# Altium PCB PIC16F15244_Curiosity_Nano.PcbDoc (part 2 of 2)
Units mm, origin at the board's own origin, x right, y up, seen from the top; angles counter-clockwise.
Board outline 50.8 x 20.32 mm, 4 copper layers (Top-Layer, Ground Plane, Power Plane, Bottom Layer), stack 1.59 mm thick; 59 components, 67 nets, 348 pads, 148 vias.
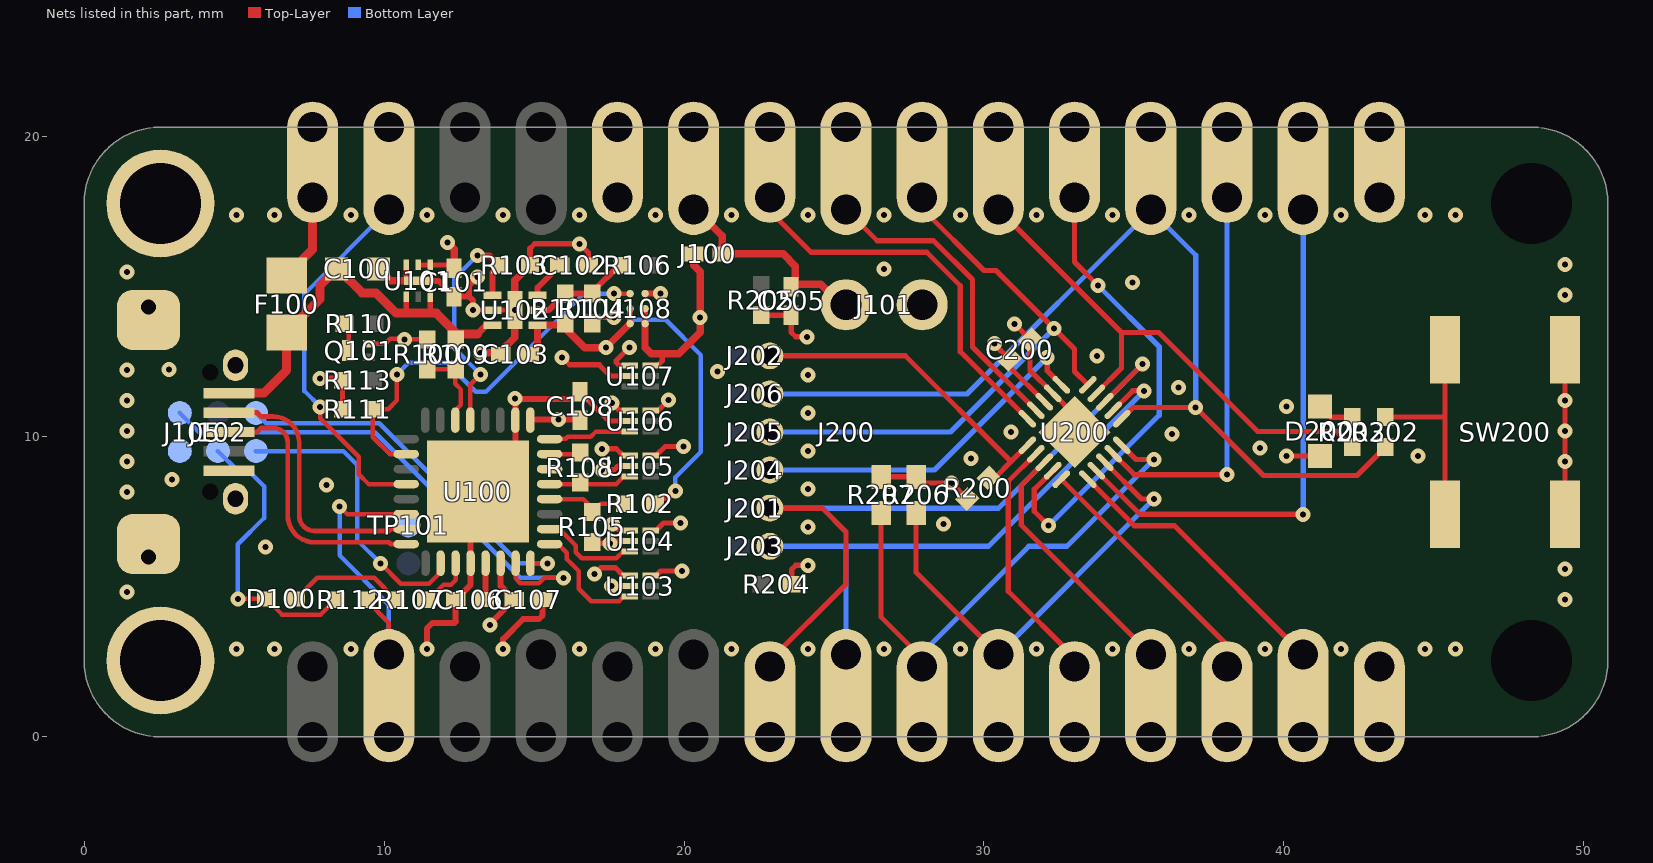
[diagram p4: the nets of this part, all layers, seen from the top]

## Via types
v1: diameter 0.5, hole 0.2, Top-Layer to Bottom Layer, 144 vias
v2: diameter 0.5, hole 0.2, Top-Layer to Bottom Layer, tented both sides, 2 vias
v3: diameter 0.5, hole 0.2, Top-Layer to Bottom Layer, tented top, 2 vias

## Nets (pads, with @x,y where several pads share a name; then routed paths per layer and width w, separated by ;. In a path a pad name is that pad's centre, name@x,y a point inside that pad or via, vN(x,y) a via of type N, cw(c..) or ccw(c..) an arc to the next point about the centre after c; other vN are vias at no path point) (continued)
GND: C100.1 C101.1 C102.2 C103.1 C106.1 C107.2 C108.2 C200.2 C205.2 J102.2 J105.5 J200.15 J200.16 J200.26 pad.666 Q101.2 R100.2 R103.2 R104.1 R105.1 R111.2 R113.2 R204.2 R205.2 SW200.1 SW200.2 TP101.1 U100.10 U100.28 U100.33 U101.3 U101.7 U102.2 U102.7 U103.2 U104.2 U105.2 U106.2 U107.2 U108.C1 U200.17 U200.21 | length 54.1
  Top-Layer w0.15: Q101.2@9.5,13.1 10.035,13.1 10.21,13.275 10.65,13.275 v1(10.675,13.25) R100.2@11.439,13.25
  Top-Layer w0.175: v1(7.87,11.95) 8.619,11.95 R111.2@8.619,10.922 ; U101.3@10.739,15.725 10.739,15.2 U101.7@11.139,15.2 ; v1(12.965,14.225) U102.2@13.615,14.225 v1(14.365,14.225) ; 14.865,16.275 15.026,16.436 15.615,16.436 v1(16.517,16.436) 16.815,16.138 C102.2@16.815,15.725 ; v1(15.94,12.65) 16.19,12.4 17.17,12.4 17.545,12.025 U107.2@18.189,12.025 ; C108.2@16.518,11.5 17.493,10.525 U106.2@18.189,10.525 ; R104.1@16.94,13.775 17.14,13.975 v1(17.659,13.975) ; R105.1@17.015,6.525 17.09,6.45 v1(17.54,6.45) 17.615,6.525 U104.2@18.189,6.525 ; v1(17.264,8.9) 17.677,8.9 17.803,9.025 U105.2@18.189,9.025 ; v1(17.59,5.025) U103.2@18.189,5.025 ; R205.2@22.581,14.054 23.571,14.054 23.571,13.487 23.724,13.335 v1(24.105,13.335) ; R204.2@23.589,5.085 23.589,5.58 23.724,5.715 v1(24.13,5.715) ; v1(31.013,13.767) C200.2@31.534,13.246 ; C200.2@31.533,13.245 31.533,12.213 U200.17@32.295,11.45 33.02,10.726 U200.21@33.02,10.16 ; SW200.2@49.371,7.41 v1(49.371,9.173) v1(49.371,10.189) v1(49.371,11.205) SW200.1@49.371,12.91
  Top-Layer w0.2: U101.7@11.139,15.2 11.814,15.2 C101.1@12.339,14.675 12.84,14.675 ; v1(11.43,2.921) 11.43,3.615 11.615,3.8 12.343,3.8 12.393,3.85 12.39,3.853 C106.1@12.39,4.575 12.884,5.069 U100.28@12.884,5.787 12.884,7.909 U100.33@13.139,8.164 ; v1(12.965,14.225) 12.965,14.55 12.84,14.675 ; v1(13.115,15.325) 12.84,15.05 12.84,14.675 ; U100.33@13.149,8.174 14.376,9.401 U100.10@14.376,10.556 14.376,11.112 14.523,11.259 16.277,11.259 C108.2@16.518,11.5 ; v1(13.97,2.921) 13.97,3.255 14.64,3.925 15.165,3.925 15.29,4.05 C107.2@15.29,4.575 ; R103.2@14.865,15.725 14.865,16.275 ; U108.C1@18.702,14.775 v1(19.215,14.775)
  Top-Layer w0.25: C100.1@9.816,15.597 10.214,15.2 U101.7@10.739,15.2 ; v1@13.165,12.8 v1(13.215,12.8) C103.1@13.895,12.8 ; C103.1@13.895,12.75 C103.1@13.895,12.8 ; R103.2@14.865,15.725 14.365,15.225 v1(14.365,14.225) 14.365,13.317 13.895,12.847 C103.1@13.895,12.8
  other v1: 5.08,2.921 6.35,2.921 8.89,2.921 16.51,2.921 19.05,2.921 21.59,2.921 24.13,2.921 26.67,2.921 29.21,2.921 31.75,2.921 34.29,2.921 36.83,2.921 39.37,2.921 41.91,2.921 44.704,2.921 45.72,2.921 49.371,4.572 1.429,4.826 49.371,5.588 24.13,6.985 28.651,7.087 1.429,8.157 24.13,8.255 2.925,8.575 1.429,9.173 29.562,9.276 44.475,9.356 24.13,9.525 39.205,9.63 36.271,10.089 30.893,10.168 1.429,10.189 24.13,10.795 40.081,11.006 1.429,11.205 14.373,11.284 36.478,11.647 24.13,12.065 21.115,12.175 1.429,12.221 2.825,12.238 33.77,12.7 49.371,14.732 34.956,15.151 1.429,15.494 26.67,15.596 49.371,15.748 5.08,17.399 6.35,17.399 8.89,17.399 11.43,17.399 13.97,17.399 16.51,17.399 19.05,17.399 21.59,17.399 24.13,17.399 26.67,17.399 29.21,17.399 31.75,17.399 34.29,17.399 36.83,17.399 39.37,17.399 41.91,17.399 44.704,17.399 45.72,17.399
  other v2: 6.05,6.325 8.088,8.4
ID_SYS: J200.2 R112.2 U100.22 | length 10.5
  Top-Layer w0.15: v1(8.515,7.675) 8.766,7.424 U100.22@10.74,7.424 ; R112.2@9.39,4.575 10.16,3.805 J200.2@10.16,2.743 J200.2@10.16,2.54
  Bottom Layer w0.15: v1(8.515,7.675) 8.515,6.05 10.16,4.405 J200.2@10.16,2.54
NetC102_1: C102.1 U102.6 | length 1.3
  Top-Layer w0.2: U102.6@15.115,14.725 15.115,14.975 C102.1@15.865,15.725
NetD100_1: D100.1 R107.1 | length 3.9
  Top-Layer w0.15: D100.1@7.071,4.6 7.768,5.297 9.669,5.297 R107.1@10.39,4.575
NetD200_1: D200.1 R203.2 | length 1.2
  Top-Layer w0.175: D200.1@41.201,11.006 41.551,10.656 R203.2@42.28,10.656
NetQ101_3: Q101.3 R110.1 | length 1
  Top-Layer w0.15: R110.1@8.674,13.7 8.815,13.559 Q101.3@8.815,12.8
NetR202_2: R202.2 SW200.3 SW200.4 | length 7.5
  Top-Layer w0.175: R202.2@43.385,10.656 45.371,10.656 ; SW200.4@45.371,7.41 45.371,10.656 ; SW200.3@45.371,12.91 45.371,10.656
RA0_ICSPDAT: J204.2 U200.16 | length 11.9
  Top-Layer w0.175: v1(32.106,12.649) 32.106,12.206 U200.16@32.578,11.733
  Bottom Layer w0.175: J204.2@22.86,8.89 28.346,8.89 v1(32.106,12.649)
RA1_ICSPCLK_ANA1: J200.22 J205.2 U200.15 | length 19.7
  Top-Layer w0.175: J200.22@27.94,17.983 27.94,17.602 29.997,15.545 30.404,15.545 v1(32.334,13.614) 33.02,12.929 33.02,12.175 U200.15@33.462,11.733
  Bottom Layer w0.175: J205.2@22.86,10.16 28.88,10.16 v1(32.334,13.614)
RA2_LED0_ANA2: J200.21 R203.1 U200.14 | length 17.5
  Top-Layer w0.175: J200.21@30.48,17.577 34.582,13.475 ; U200.14@33.745,11.45 34.582,12.288 34.582,13.475 ; R203.1@42.28,9.656 41.761,10.175 39.126,10.175 35.827,13.475 34.582,13.475
RA3_M\C\L\R\: J202.2 R200.2 U200.1 | length 11.3
  Top-Layer w0.175: J202.2@22.86,12.7 27.375,12.7 30.902,9.173 ; R200.2@30.072,8.629 30.357,8.629 30.902,9.173 ; U200.1@31.447,9.718 30.902,9.173
RA4_ANA4: J200.24 U200.20 | length 13.2
  Top-Layer w0.175: J200.24@22.86,17.983 22.86,17.526 24.232,16.154 28.092,16.154 29.21,15.037 29.21,12.839 U200.20@31.447,10.602
RA5_ANA5: J200.23 U200.19 | length 10.4
  Top-Layer w0.175: J200.23@25.4,17.577 26.441,16.535 28.321,16.535 29.616,15.24 29.616,12.998 U200.19@31.73,10.885
RB4_I2C_SDA: J200.9 R207.2 U200.10 | length 19.6
  Top-Layer w0.16: R207.2@26.568,7.468 26.568,3.988 27.94,2.616 J200.9@27.94,2.337 J200.9@27.94,0.508
  Top-Layer w0.175: U200.10@34.593,9.718 35.066,9.246 v1(35.662,9.246)
  Bottom Layer w0.175: J200.9@27.94,2.337 27.94,2.794 31.496,6.35 32.766,6.35 v1(35.662,9.246)
RB5_ANB5: J200.18 U200.9 | length 13.3
  Top-Layer w0.175: U200.9@34.31,9.435 35.008,8.738 v1(38.1,8.738)
  Bottom Layer w0.175: v1(38.1,8.738) J200.18@38.1,17.983
RB6_I2C_SCL: J200.10 R206.2 U200.8 | length 17.2
  Top-Layer w0.175: R206.2@27.737,7.468 27.737,5.486 J200.10@30.48,2.743 J200.10@30.48,0.855 ; U200.8@34.028,9.152 35.255,7.925 v1(35.662,7.925)
  Bottom Layer w0.175: J200.10@30.48,2.743 v1(35.662,7.925)
RB7_ANB7: J200.17 U200.7 | length 17.7
  Top-Layer w0.175: U200.7@33.745,8.87 35.198,7.417 v1(40.64,7.417)
  Bottom Layer w0.175: v1(40.64,7.417) J200.17@40.64,17.577
RC0_UART_TX: J200.7 J201.2 U200.13 | length 24.6
  Top-Layer w0.175: J200.7@22.86,2.337 22.86,2.54 25.4,5.08 25.4,6.831 24.611,7.62 J201.2@22.86,7.62 ; U200.13@34.028,11.168 v1(35.281,12.421)
  Bottom Layer w0.175: J201.2@22.86,7.62 30.48,7.62 v1(35.281,12.421)
RC1_UART_RX: J200.8 J203.2 U200.12 | length 19.5
  Top-Layer w0.175: U200.12@34.31,10.885 34.957,11.532 v1(35.331,11.532)
  Bottom Layer w0.175: J203.2@22.86,6.35 25.4,6.35 ; J200.8@25.4,2.743 25.4,6.35 ; v1(35.331,11.532) 30.15,6.35 25.4,6.35
RC2_SW0_ANC2: J200.19 J206.2 R202.1 U200.11 | length 32.7
  Top-Layer w0.175: U200.11@34.593,10.602 34.964,10.973 v1(37.059,10.973) 39.319,8.712 42.441,8.712 R202.1@43.385,9.656
  Bottom Layer w0.175: J206.2@22.86,11.43 29.439,11.43 35.56,17.551 37.059,16.053 v1(37.059,10.973)
RC3_ANC3: J200.20 U200.4 | length 16.4
  Top-Layer w0.175: v1(32.156,7.036) 31.674,7.518 31.674,8.248 U200.4@32.295,8.87 ; J200.20@33.02,17.983 33.02,15.824 v1(33.807,15.037)
  Bottom Layer w0.175: v1(32.156,7.036) 35.839,10.719 35.839,13.005 v1(33.807,15.037) ; J200.20@33.02,17.526 J200.20@33.02,17.983
RC4_SPI_MISO: J200.12 U200.3 | length 8.5
  Top-Layer w0.175: U200.3@32.012,9.152 31.242,8.382 31.242,7.061 J200.12@35.56,2.743
RC5_SPI_MOSI: J200.11 U200.2 | length 8.4
  Top-Layer w0.175: U200.2@31.73,9.435 30.81,8.516 30.81,4.851 33.02,2.642 J200.11@33.02,2.337
RC6_SPI_SCK: J200.13 U200.5 | length 8.5
  Top-Layer w0.175: U200.5@32.578,8.587 38.1,3.065 J200.13@38.1,2.337
RC7_SPI_SS: J200.14 U200.6 | length 9.6
  Top-Layer w0.175: U200.6@33.462,8.587 35.013,7.036 36.347,7.036 J200.14@40.64,2.743
REG_ADJUST: R101.2 R104.2 R106.1 U102.5 | length 3.4
  Top-Layer w0.2: U102.5@15.115,14.225 15.49,14.225 R101.2@16.04,14.775 16.965,14.775 16.965,14.85 R106.1@17.84,15.725
REG_ENABLE: R103.1 U100.13 U102.1 | length 8.3
  Top-Layer w0.15: U100.13@12.876,10.556 12.876,11.736 v1(13.215,12.075)
  Top-Layer w0.2: v1(13.115,16.05) 13.508,16.05 13.833,15.725 R103.1@13.865,15.725 13.615,15.475 U102.1@13.615,14.725
  Bottom Layer w0.15: v1(13.115,16.05) 12.34,15.275 12.34,12.95 v1(13.215,12.075)
RESERVED: U100.6
S0_0_RX: R108.1 U100.5 U105.3 | length 2.8
  Top-Layer w0.15: U100.5@15.52,8.424 17.74,8.424 17.991,8.675 U105.3@18.189,8.675
S0_2_TX: R108.2 U100.7 | length 1
  Top-Layer w0.15: U100.7@15.52,9.424 R108.2@16.515,9.424
S0_3_CLK: U100.8 U106.3 | length 2.8
  Top-Layer w0.15: U100.8@15.52,9.937 16.055,9.937 16.119,10 16.89,10 17.065,10.175 U106.3@18.189,10.175
S1_0_TX: U100.1 U103.3 | length 4
  Top-Layer w0.15: U100.1@15.52,6.424 15.797,6.424 16.09,6.131 16.09,5.925 16.49,5.525 16.49,4.934 16.905,4.519 17.834,4.519 17.99,4.675 U103.3@18.189,4.675
S1_1_RX: U100.2 U104.3 | length 3.3
  Top-Layer w0.15: U100.2@15.52,6.924 15.841,6.924 16.39,6.375 16.39,6.156 16.596,5.95 17.74,5.95 17.965,6.175 U104.3@18.189,6.175
S\R\S\T\: J102.6 U100.26 | length 9.9
  Top-Layer w0.15: v3(9.885,5.777) 10.562,5.1 11.498,5.1 11.884,5.486 U100.26@11.884,5.787
  Bottom Layer w0.15: J102.6@5.73,9.525 8.64,9.525 9.1,9.065 9.1,6.562 v3(9.885,5.777)
SHIELD: J105.6 J105.7 J105.8 J105.9
STATUS_LED: R107.2 U100.27 | length 1.8
  Top-Layer w0.15: R107.2@11.39,4.575 11.493,4.575 11.993,5.075 12.24,5.075 12.393,5.228 U100.27@12.393,5.777
SWCLK: J102.1 U100.31 | length 17.3
  Top-Layer w0.15: U100.31@14.384,5.787 14.384,5.281 14.544,5.122 15.165,5.122 15.34,5.297 v1(15.99,5.297)
  Bottom Layer w0.15: J102.1@3.19,10.795 3.835,10.15 9.69,10.15 14.543,5.297 v1(15.99,5.297)
SWDIO: J102.5 U100.32 | length 12.4
  Top-Layer w0.15: U100.32@14.88,5.784 v1(15.449,5.784)
  Bottom Layer w0.15: J102.5@5.73,10.795 6.075,10.45 9.84,10.45 14.506,5.784 v1(15.449,5.784)
USBD_N: J105.2 U100.23 | length 9.2
  Top-Layer w0.16: J105.2@4.83,10.81 5.77,10.81 5.905,10.675 6.3,10.675 cw(c6.3,9.805) 7.17,9.805 7.17,7.375 ccw(c7.681,7.375) 7.681,6.864 10.165,6.864 10.225,6.924 U100.23@10.74,6.924
USBD_P: J105.3 U100.24 | length 9.2
  Top-Layer w0.16: J105.3@4.83,10.16 5.77,10.16 5.905,10.295 6.3,10.295 cw(c6.3,9.805) 6.79,9.805 6.79,7.375 ccw(c7.681,7.375) 7.681,6.484 10.165,6.484 10.225,6.424 U100.24@10.74,6.424
V\O\F\F\: J200.29 U100.20 | length 12.5
  Top-Layer w0.15: v1(7.87,11) 7.87,10.621 9.153,9.338 9.153,8.754 9.483,8.424 U100.20@10.74,8.424
  Bottom Layer w0.15: v1(7.87,11) 7.346,11.524 7.346,14.763 J200.29@10.16,17.577
VBUS: F100.1 J200.30 | length 2.8
  Top-Layer w0.3: F100.1@6.75,15.377 7.62,16.247 J200.30@7.62,17.78
VBUS_ADC: R100.1 R109.1 U100.14 | length 2.8
  Top-Layer w0.15: R100.1@11.439,12.25 12.376,12.25 12.376,11.764 12.565,11.575 12.565,11.068 12.376,10.879 U100.14@12.376,10.556
VCC_EDGE: C205.1 J100.2 J101.1 J200.25 | length 7.4
  Top-Layer w0.25: J200.25@20.32,17.645 21.27,16.695 J100.2@21.27,16.098 23.307,16.098 23.715,15.691 C205.1@23.715,15.01 ; C205.1@23.571,15.004 23.655,15.088 24.56,15.088 25.246,14.402 J101.1@25.4,14.402
VCC_LEVEL: J100.1 U103.6 U104.6 U105.6 U106.6 U107.6 U108.A1 U108.B1 | length 11.2
  Top-Layer w0.175: U103.6@18.889,5.375 19.065,5.375 19.215,5.525 v1(19.94,5.525) ; U104.6@18.889,6.875 19.065,6.875 19.315,7.125 v1(19.89,7.125) ; U105.6@18.889,9.375 18.902,9.388 19.087,9.388 19.375,9.675 v1(19.99,9.675) ; U106.6@18.889,10.875 19.14,10.875 v1(19.49,11.225) ; U107.6@18.889,12.375 18.902,12.388 19.137,12.388 19.275,12.525 19.275,12.767
  Top-Layer w0.2: U108.A1@18.702,13.775 U108.B1@18.702,14.275
  Top-Layer w0.225: 18.702,12.963 U108.A1@18.702,13.775
  Top-Layer w0.25: 18.714,12.963 18.909,12.767 19.275,12.767 19.822,12.767 20.54,13.485 v1(20.54,13.985) 20.54,15.5 20.32,15.72 J100.1@20.32,16.2
VCC_MCU_CORE: C106.2 U100.29 | length 1.2
  Top-Layer w0.2: C106.2@13.34,4.575 13.384,4.619 U100.29@13.384,5.787
VCC_P3V3: C101.2 C107.1 C108.1 D100.2 J102.4 R112.1 U100.9 U100.30 U101.1 U101.2 U103.1 U104.1 U105.1 U106.1 U107.1 | length 21.4
  Top-Layer w0.15: v1(5.125,4.6) D100.2@6.071,4.6 6.596,4.075 7.89,4.075 R112.1@8.39,4.575 ; D100.2@5.99,4.575 D100.2@6.14,4.425
  Top-Layer w0.175: U101.2@11.139,15.725 12.239,15.725 C101.2@12.339,15.625 ; v1(17.015,5.425) 17.228,5.638 17.706,5.638 17.968,5.375 U103.1@18.189,5.375 ; v1(17.264,9.6) 17.74,9.6 17.965,9.375 U105.1@18.189,9.375 ; v1(17.599,11.125) 17.849,10.875 U106.1@18.189,10.875 ; v1(17.615,7.1) 17.84,6.875 U104.1@18.189,6.875 ; U107.1@18.189,12.375 17.843,12.375 17.74,12.478 17.74,12.541 18.172,12.973 v1(18.189,12.973)
  Top-Layer w0.2: v1(13.54,3.725) 13.54,3.775 C107.1@14.34,4.575 13.884,5.031 U100.30@13.884,5.787 ; U100.9@14.876,10.581 v1(15.815,10.581) 16.429,10.581 C108.1@16.515,10.495
  Top-Layer w0.25: v1(12.115,16.475) 12.339,16.251 C101.2@12.339,15.625
  Bottom Layer w0.15: J102.4@4.46,9.525 5.135,8.85 5.5,8.85 6,8.35 6,7.292 5.125,6.417 v1(5.125,4.6)
VCC_REGULATOR: C103.2 R101.1 R102.2 U102.4 U108.A2 U108.B2 | length 15.2
  Top-Layer w0.175: R102.2@19.039,7.875 19.113,7.95 19.465,7.95 v1(19.715,8.2) ; v1@19.765,8.175 v1@19.79,8.2
  Top-Layer w0.2: R101.1@16.04,13.62 R101.1@16.04,13.775 ; U108.A2@18.202,13.775 U108.B2@18.202,14.275
  Top-Layer w0.225: v1(17.4,12.973) U108.A2@18.202,13.775
  Top-Layer w0.24: C103.2@14.845,12.75 15.115,13.02 U102.4@15.115,13.725 15.99,13.725 R101.1@16.04,13.775
  Top-Layer w0.25: R101.1@16.04,13.62 16.687,12.973 v1(17.4,12.973)
  Bottom Layer w0.15: v1(17.4,12.973) 18.327,13.9 19.387,13.9 20.565,12.722 20.565,9.504 19.715,8.654 v1(19.715,8.2)
VCC_TARGET: C200.1 D200.2 J101.2 R200.1 R206.1 R207.1 U200.18 | length 6.9
  Top-Layer w0.175: R207.1@26.568,8.668 R206.1@27.737,8.668 27.946,8.458 v1(28.913,8.458) R200.1@29.443,7.929 ; v1(30.353,13.106) 30.353,13.081 C200.1@30.861,12.573 30.861,12.319 U200.18@32.012,11.168 ; v1(40.081,9.356) D200.2@41.201,9.356
VCC_VBUS: C100.2 F100.2 J105.1 R109.2 U101.4 U101.6 U102.3 | length 13.8
  Top-Layer w0.175: 10.739,14.151 U101.4@10.739,14.675 ; 11.539,14.151 U101.6@11.539,14.675
  Top-Layer w0.24: 13.115,13.425 13.415,13.725 U102.3@13.615,13.725
  Top-Layer w0.3: J105.1@4.83,11.46 5.989,11.46 6.75,12.221 F100.2@6.75,13.477 7.87,14.597 7.87,15.048 C100.2@8.419,15.597 ; C100.2@8.444,15.622 9.267,14.8 9.724,14.8 10.399,14.125 11.74,14.125 12.389,13.476 R109.2@12.389,13.425 ; R109.2@12.389,13.25 R109.2@12.389,13.425 ; 13.115,13.425 R109.2@12.389,13.425
VTG_ADC: R102.1 R105.2 U100.4 | length 2.8
  Top-Layer w0.15: U100.4@15.52,7.924 16.64,7.924 R105.2@17.003,7.561 ; R105.2@16.94,7.499 R105.2@17.003,7.561 ; R102.1@18.039,7.775 17.216,7.775 R105.2@17.003,7.561
VTG_EN: R111.1 U100.18 U108.C2 | length 13.8
  Top-Layer w0.15: v1(10.425,12.075) 10.425,11.212 10.135,10.922 R111.1@9.627,10.922 9.627,9.982 10.185,9.424 U100.18@10.74,9.424 ; v1(17.659,14.775) U108.C2@18.202,14.775
  Bottom Layer w0.15: v1(10.425,12.075) 10.825,12.475 12.09,12.475 13.058,11.507 13.397,11.507 16.665,14.775 v1(17.659,14.775)
pads on no net: J102.3 J105.0 J105.4 J105.10 J105.11 J200.0 J200.1 Q101.0 U101.0 U101.5 U103.0 U104.0 U105.0 U106.0 U107.0

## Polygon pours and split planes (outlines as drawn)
GND on Bottom Layer "Bottom Layer-GND" (solid, remove dead copper, pour order 2): 50.8,20.32 50.8,0 0,0 0,20.32
GND on Top-Layer "Top Layer-GND" (solid, remove dead copper, pour order 4): 50.8,20.32 50.8,0 0,0 0,20.32
GND on Ground Plane (split plane): 48.459,19.802 48.656,19.773 48.85,19.724 49.038,19.657 49.218,19.572 49.389,19.469 49.549,19.351 49.697,19.217 49.831,19.069 49.949,18.909 50.052,18.738 50.137,18.558 50.204,18.37 50.253,18.176 50.282,17.979 50.291,17.796 50.29,17.78 50.29,2.54 50.291,2.524 50.282,2.341 50.253,2.144 50.204,1.95 50.137,1.762 50.052,1.582 49.949,1.411 49.831,1.251 49.697,1.103 49.549,0.969 49.389,0.851 49.218,0.748 49.038,0.663 48.85,0.596 48.656,0.547 48.459,0.518 48.276,0.509 48.26,0.51 2.54,0.51 2.524,0.509 2.341,0.518 2.144,0.547 1.95,0.596 1.762,0.663 1.582,0.748 1.411,0.851 1.251,0.969 1.103,1.103 0.969,1.251 0.851,1.411 0.748,1.582 0.663,1.762 0.596,1.95 0.547,2.144 0.518,2.341 0.509,2.524 0.51,2.54 0.51,17.78 0.509,17.796 0.518,17.979 0.547,18.176 0.596,18.37 0.663,18.558 0.748,18.738 0.851,18.909 0.969,19.069 1.103,19.217 1.251,19.351 1.411,19.469 1.582,19.572 1.762,19.657 1.95,19.724 2.144,19.773 2.341,19.802 2.524,19.811 2.54,19.81 48.26,19.81 48.276,19.811
VCC_P3V3 on Power Plane (split plane): 2.54,19.81 18.913,19.81 18.899,14.6 18.899,4.55 18.899,0.51 2.54,0.51 2.524,0.509 2.341,0.518 2.144,0.547 1.95,0.596 1.762,0.663 1.582,0.748 1.411,0.851 1.251,0.969 1.103,1.103 0.969,1.251 0.851,1.411 0.748,1.582 0.663,1.762 0.596,1.95 0.547,2.144 0.518,2.341 0.509,2.524 0.51,2.54 0.51,17.78 0.509,17.796 0.518,17.979 0.547,18.176 0.596,18.37 0.663,18.558 0.748,18.738 0.851,18.909 0.969,19.069 1.103,19.217 1.251,19.351 1.411,19.469 1.582,19.572 1.762,19.657 1.95,19.724 2.144,19.773 2.341,19.802 2.524,19.811
VCC_TARGET on Power Plane (split plane): 48.459,19.802 48.656,19.773 48.85,19.724 49.038,19.657 49.218,19.572 49.389,19.469 49.549,19.351 49.697,19.217 49.831,19.069 49.949,18.909 50.052,18.738 50.137,18.558 50.204,18.37 50.253,18.176 50.282,17.979 50.291,17.796 50.29,17.78 50.29,2.54 50.291,2.524 50.282,2.341 50.253,2.144 50.204,1.95 50.137,1.762 50.052,1.582 49.949,1.411 49.831,1.251 49.697,1.103 49.549,0.969 49.389,0.851 49.218,0.748 49.038,0.663 48.85,0.596 48.656,0.547 48.459,0.518 48.276,0.509 48.26,0.51 19.201,0.51 19.201,4.399 21.715,4.399 21.754,4.404 21.791,4.419 21.822,4.443 21.846,4.474 21.861,4.511 21.866,4.55 21.866,14.6 21.861,14.639 21.846,14.676 21.822,14.707 21.791,14.731 21.754,14.746 21.715,14.751 19.202,14.751 19.216,19.81 48.26,19.81 48.276,19.811
VCC_LEVEL on Power Plane (split plane): 21.564,4.701 19.201,4.701 19.201,14.449 21.564,14.449

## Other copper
Bottom Layer:
  pour cut-out: 23.45,13.356 23.45,5.694 21.335,5.694 21.335,13.356
Power Plane (plane layer: these items are gaps in the copper):
  lines w0.3: 19.05,0 19.05,4.55 ; 19.066,20.32 19.05,14.6 ; 19.05,4.55 19.05,14.6 ; 19.05,4.55 21.715,4.55 21.715,14.6 19.05,14.6

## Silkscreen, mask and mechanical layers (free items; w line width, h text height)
Top Overlay:
  circle w0.4: c6.346,1.365 r0.2
  lines w0.15: 4.064,4.039 19.504,4.039 19.64,4.175 19.64,16.15 19.534,16.256 4.064,16.256
  text "GND" at 5.497,16.58 h0.9 r90
  text "RA4" at 21.895,15.972 h0.75
  text "RA1" at 27.065,15.972 h0.75
  text "RC3" at 32.02,15.972 h0.75
  text "RB5" at 37.109,15.972 h0.75
  text "GND" at 42.18,15.972 h0.75
  text "RA5" at 24.4,15.693 h0.75
  text "RA2" at 29.48,15.693 h0.75
  text "RC2" at 34.56,15.693 h0.75
  text "RB7" at 39.64,15.693 h0.75
  text "SW0" at 46.371,14.383 h0.75
  text "POWER" at 24.921,12.497 h0.75
  text "LED0" at 40.731,12.354 h0.75
  text "I2C" at 26.215,9.55 h0.75
  text "RA2" at 41.067,7.821 h0.75
  text "DEBUG" at 7.25,6.686 h0.9 r90
  text "b" at 35.107,6.659 h8.89
  text "'.Target_Name'" at 24.765,5.461 h0.9
  text "RC2" at 46.371,5.213 h0.75
  text "PS" at 5.946,5.175 h0.75
  text "PIC® / MCU" at 35.56,5.08 h2.2
  text "'.Target_Name' / CURIOSITY NANO" at 21.995,4.785 h1.35 r90
  text "RC1" at 24.525,3.888 h0.75
  text "RB6" at 29.48,3.888 h0.75
  text "RC4" at 34.56,3.888 h0.75
  text "RC7" at 39.64,3.888 h0.75
  text "RC0" at 21.86,3.609 h0.75
  text "RB4" at 26.94,3.609 h0.75
  text "RC5" at 32.02,3.609 h0.75
  text "RC6" at 37.1,3.609 h0.75
  text "GND" at 42.18,3.609 h0.75
  text "GND" at 5.497,1.34 h0.9 r90
Bottom Overlay:
  lines w0.15: 21.275,5.625 21.275,13.42 ; 23.575,5.625 23.575,13.42 ; 24.825,13.42 23.575,13.42 ; 25.975,13.42 26.625,13.42 26.625,5.625 18,5.625 18,13.42 23.575,13.42
  text "GND" at 5.497,18.98 h0.9 r90
  text "VBUS" at 7.995,16.722 h0.75 r90
  text "D3" at 13.325,15.972 h0.75
  text "GND" at 18.78,15.972 h0.75
  text "RA4" at 23.86,15.972 h0.75
  text "RA1" at 28.815,15.972 h0.75
  text "RC3" at 34.02,15.972 h0.75
  text "RB5" at 39.091,15.972 h0.75
  text "GND" at 44.18,15.972 h0.75
  text "VOFF" at 11.535,15.693 h0.75
  text "D0" at 15.865,15.693 h0.75
  text "VTG" at 21.32,15.693 h0.75
  text "RA5" at 26.4,15.693 h0.75
  text "RA2" at 31.48,15.693 h0.75
  text "RC2" at 36.56,15.693 h0.75
  text "RB7" at 41.64,15.693 h0.75
  text "CONNECTIONS" at 24.199,14.025 h0.7
  text "Microchip © 2019" at 48.691,13.079 h2
  text "DEBUGGER" at 17.665,12.397 h0.75 r90
  text "D3" at 20.945,12.335 h0.75
  text "RA3" at 26.308,12.335 h0.75
  text "TARGET" at 27.725,11.647 h0.75 r90
  text "D2" at 20.945,11.06 h0.75
  text "RC2" at 26.308,11.06 h0.75
  text "c" at 16.415,10.475 h6.8
  text "D1" at 20.945,9.785 h0.75
  text "RA1" at 26.308,9.785 h0.75
  text "D0" at 20.945,8.51 h0.75
  text "RA0" at 26.308,8.51 h0.75
  text "CDC" at 19.179,7.985 h0.75 r90
  text "RX" at 20.945,7.235 h0.75
  text "RC0" at 26.308,7.235 h0.75
  text "t" at 14.776,7.05 h4.57
  text "GND" at 10.115,6.672 h0.75
  text "TX" at 20.945,5.96 h0.75
  text "RC1" at 26.308,5.96 h0.75
  text "'.AN_PCB' Rev'.PCB_rev'" at 47.403,5.544 h2
  text "BOOT" at 10.115,5.402 h0.75
  text "CDC" at 14.955,4.825 h0.75
  text "R" at 31.928,4.597 h2.4
  text "ID" at 10.722,3.888 h0.75
  text "TX" at 15.865,3.888 h0.75
  text "D2" at 20.945,3.888 h0.75
  text "RC1" at 26.275,3.888 h0.75
  text "RB6" at 31.48,3.888 h0.75
  text "RC4" at 36.56,3.888 h0.75
  text "RC7" at 41.64,3.888 h0.75
  text "GND" at 5.497,3.74 h0.9 r90
  text "NC" at 8.245,3.609 h0.75
  text "RX" at 13.325,3.609 h0.75
  text "D1" at 18.28,3.609 h0.75
  text "RC0" at 23.86,3.609 h0.75
  text "RB4" at 28.931,3.609 h0.75
  text "RC5" at 34.02,3.609 h0.75
  text "RC6" at 39.1,3.609 h0.75
  text "GND" at 44.18,3.609 h0.75
Board (M1):
  the board outline again, w0.1
Conn. Pos. (M4):
  circle w0.35: c43.18,2.337 r0.65
  circle w0.35: c43.18,17.983 r0.65
  circle w0.35: c40.64,2.743 r0.65
  circle w0.35: c40.64,17.577 r0.65
  circle w0.35: c38.1,17.983 r0.65
  circle w0.35: c38.1,2.337 r0.65
  circle w0.35: c22.86,17.983 r0.65
  circle w0.35: c22.86,2.337 r0.65
  circle w0.35: c25.4,2.743 r0.65
  circle w0.35: c25.4,17.577 r0.65
  circle w0.35: c27.94,2.337 r0.65
  circle w0.35: c27.94,17.983 r0.65
  circle w0.35: c30.48,2.743 r0.65
  circle w0.35: c30.48,17.577 r0.65
  circle w0.35: c33.02,2.337 r0.65
  circle w0.35: c33.02,17.983 r0.65
  circle w0.35: c35.56,2.743 r0.65
  circle w0.35: c35.56,17.577 r0.65
  circle w0.35: c20.32,17.577 r0.65
  circle w0.35: c20.32,2.743 r0.65
  circle w0.35: c17.78,17.983 r0.65
  circle w0.35: c17.78,2.337 r0.65
  circle w0.35: c15.24,17.577 r0.65
  circle w0.35: c15.24,2.743 r0.65
  circle w0.35: c12.7,17.983 r0.65
  circle w0.35: c12.7,2.337 r0.65
  circle w0.35: c10.16,17.577 r0.65
  circle w0.35: c10.16,2.743 r0.65
  circle w0.35: c7.62,2.337 r0.65
  circle w0.4: c2.54,2.54 r1.6
  circle w0.4: c48.26,2.54 r1.6
  circle w0.35: c7.62,17.983 r0.65
  circle w0.4: c48.26,17.78 r1.6
  circle w0.4: c2.54,17.78 r1.6
  region: 1.04,14.884 1.04,12.784 2.94,12.784 2.94,14.884
  region: 2.94,5.484 2.94,7.584 1.04,7.584 1.04,5.484
  region: 5.68,11.285 5.68,11.635 3.98,11.635 3.98,11.285
  region: 5.68,10.635 5.68,10.985 3.98,10.985 3.98,10.635
  region: 5.68,9.985 5.68,10.335 3.98,10.335 3.98,9.985
  region: 5.68,9.335 5.68,9.685 3.98,9.685 3.98,9.335
  region: 5.68,8.685 5.68,9.035 3.98,9.035 3.98,8.685
  lines w0.35: 6.97,0 cw(c7.62,0) 8.27,0 ; 6.97,20.32 ccw(c7.62,20.32) 8.27,20.32 ; 9.51,0 cw(c10.16,0) 10.81,0 ; 9.51,20.32 ccw(c10.16,20.32) 10.81,20.32 ; 12.05,0 cw(c12.7,0) 13.35,0 ; 12.05,20.32 ccw(c12.7,20.32) 13.35,20.32 ; 14.59,0 cw(c15.24,0) 15.89,0 ; 14.59,20.32 ccw(c15.24,20.32) 15.89,20.32 ; 17.13,0 cw(c17.78,0) 18.43,0 ; 17.13,20.32 ccw(c17.78,20.32) 18.43,20.32 ; 19.67,0 cw(c20.32,0) 20.97,0 ; 19.67,20.32 ccw(c20.32,20.32) 20.97,20.32 ; 22.21,0 cw(c22.86,0) 23.51,0 ; 22.21,20.32 ccw(c22.86,20.32) 23.51,20.32 ; 24.75,0 cw(c25.4,0) 26.05,0 ; 24.75,20.32 ccw(c25.4,20.32) 26.05,20.32 ; 27.29,0 cw(c27.94,0) 28.59,0 ; 27.29,20.32 ccw(c27.94,20.32) 28.59,20.32 ; 29.83,0 cw(c30.48,0) 31.13,0 ; 29.83,20.32 ccw(c30.48,20.32) 31.13,20.32 ; 32.37,0 cw(c33.02,0) 33.67,0 ; 32.37,20.32 ccw(c33.02,20.32) 33.67,20.32 ; 34.91,0 cw(c35.56,0) 36.21,0 ; 34.91,20.32 ccw(c35.56,20.32) 36.21,20.32 ; 37.45,0 cw(c38.1,0) 38.75,0 ; 37.45,20.32 ccw(c38.1,20.32) 38.75,20.32 ; 39.99,0 cw(c40.64,0) 41.29,0 ; 39.99,20.32 ccw(c40.64,20.32) 41.29,20.32 ; 42.53,0 cw(c43.18,0) 43.83,0 ; 42.53,20.32 ccw(c43.18,20.32) 43.83,20.32
  text "Connector Placement" at -0.05,26.425 h5
TP Pos. (M5):
  circle w0.5: c3.19,10.795 r0.25
  circle w0.5: c3.19,9.525 r0.25
  circle w0.5: c4.46,9.525 r0.25
  circle w0.5: c4.46,10.795 r0.25
  circle w0.5: c5.73,10.795 r0.25
  circle w0.5: c5.73,9.525 r0.25
  circle w0.4: c2.54,2.54 r1.6
  circle w0.4: c2.54,17.78 r1.6
  lines w0.1: 2.79,8.12 3.19,8.52 ; 2.79,12.2 3.19,11.8 ; 3.59,8.12 3.19,8.52 ; 3.59,12.2 3.19,11.8 ; 4.06,8.12 4.46,8.52 ; 4.86,8.12 4.46,8.52 ; 5.33,8.12 5.73,8.52 ; 5.33,12.2 5.73,11.8 ; 6.13,8.12 5.73,8.52 ; 6.13,12.2 5.73,11.8 ; 12.18,4.07 3.19,4.07 3.19,8.52 ; 12.18,5.82 4.46,5.82 4.46,8.52 ; 12.18,7.57 5.73,7.57 5.73,8.52 ; 12.18,12.75 5.73,12.75 5.73,11.8 ; 12.18,14.5 3.19,14.5 3.19,11.8
  text "Test Point Placement" at -0.102,26.467 h5
  text "J101-1_SWCLK" at 12.88,14.083 h1
  text "J101-5_SWD" at 12.88,12.333 h1
  text "J101-6_RST" at 12.88,6.903 h1
  text "J101-4_VCC" at 12.88,5.153 h1
  text "J101-2_GND" at 12.88,3.403 h1
  text "2x5 50mil test-point pattern" at 7.15,-2.025 h1
Dimentions (M6):
  text "Dimentions" at 0.254,26.416 h5
Test Jig (M9):
  circle w0.5: c-43.81,-5.475 r1.25
  circle w0.5: c-43.81,25.775 r1.25
  circle w0.5: c2.54,2.54 r1.5
  circle w0.5: c2.54,17.78 r1.5
  lines w0.5: -38.31,-12.225 -38.31,32.525 cw(c-36.81,32.525) -35.31,32.525 -6.31,32.525 cw(c-4.81,32.525) -3.31,32.525 -3.31,-12.225 ; -38.309,-12.225 ccw(c-36.809,-12.225) -35.309,-12.225 -6.309,-12.225 ccw(c-4.809,-12.225) -3.309,-12.225 ; -49.31,-20.225 -46.31,-23.225 86.47,-23.225 89.47,-20.226 89.47,40.5 86.47,43.5 -46.31,43.5 -49.31,40.5 -49.31,-20.225 ; 0.69,7.85 ccw(c2.19,7.85) 2.19,6.35 5.04,6.35 cw(c5.04,4.85) 6.54,4.85 6.54,4.04 ccw(c8.04,4.04) 8.04,2.54 59.19,2.54 ccw(c59.19,4.04) 60.69,4.04 60.69,16.28 ccw(c59.19,16.28) 59.19,17.78 8.04,17.78 ccw(c8.04,16.28) 6.54,16.28 6.54,15.47 cw(c5.04,15.47) 5.04,13.97 2.19,13.97 ccw(c2.19,12.47) 0.69,12.47 0.69,7.85
  text "Xplained Nano FCT" at -29.74,36.109 h10
Test Jig Pin (M10):
  circle w0.1: c76.2,2.54 r2.85
  circle w0.1: c76.2,17.78 r2.85
  circle w0.5: c2.54,17.78 r2
  circle w0.5: c2.54,17.78 r1.25
  circle w0.5: c2.54,2.54 r1.25
  circle w0.5: c2.54,2.54 r2
  circle w0.1: c2.54,17.78 r2.85
  circle w0.1: c2.54,2.54 r2.85

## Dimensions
5.98,9.525 to 5.98,10.795 on TP Pos. (M5)
49.86,2.54 to 49.86,17.78 on Conn. Pos. (M4)
7.62,19.67 to 2.54,19.38 on Conn. Pos. (M4)
35.555,0 to 33.015,0 on Conn. Pos. (M4)
2.54,0 to 1.9,10.16 on Conn. Pos. (M4)
48.26,20.32 to 48.26,0 on Dimentions (M6)
50.8,2.54 to 0,2.54 on Dimentions (M6)
2.54,0.94 to 48.26,0.94 on Conn. Pos. (M4)
2.54,20.32 to 0.94,17.78 on Conn. Pos. (M4)
0,17.78 to 2.54,19.38 on Conn. Pos. (M4)
3.19,9.275 to 2.54,0.94 on TP Pos. (M5)
2.94,9.525 to 0.94,2.54 on TP Pos. (M5)
2.94,10.795 to 0.94,2.54 on TP Pos. (M5)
